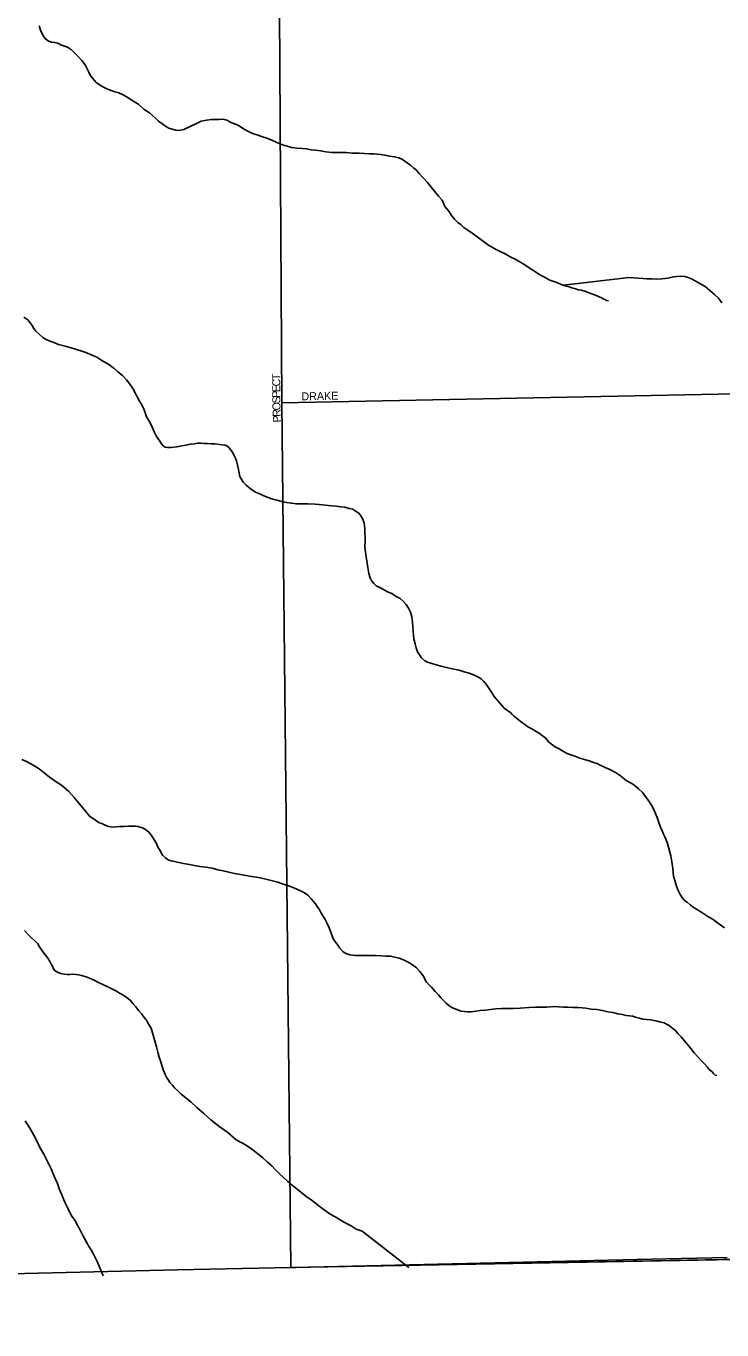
# Model space of a CAD drawing. Extents: x 2010165 to 2382125, y 1060529 to 1407316.
# Drawn here: x 2143376 to 2147720, y 1193411 to 1201555 of the extents above; entities that cross this region are included whole.
import ezdxf

# ---------------------------------------------------------------- set-up
doc = ezdxf.new("R2010")
doc.units = 0
for name, color, linetype in [('GM_X_Adjacent_County', 7, 'Continuous'), ('GM_X_City_Street', 7, 'Continuous'), ('GM_X_City_Street_Text', 7, 'Continuous'), ('GM_X_Corporation', 7, 'Continuous'), ('GM_X_County', 7, 'Continuous'), ('GM_X_Minor_River', 7, 'Continuous')]:
    doc.layers.add(name, color=color, linetype=linetype)

msp = doc.modelspace()

# ---------------------------------------------------------------- linework, layer by layer
at = {"layer": 'GM_X_Adjacent_County'}
msp.add_lwpolyline([(2158006.9, 1194141.9), (2151106.9, 1193912.6), (2145028.4, 1193800.8), (2144321.2, 1193786.8), (2140581.8, 1193696.4), (2139549.1, 1193676.6), (2134076.1, 1193549.4), (2129443.2, 1193492.7), (2126053.1, 1193488.1), (2117908.3, 1193445.4), (2113522.7, 1193410.7)], dxfattribs=at)
at = {"layer": 'GM_X_City_Street'}
for points in [[(2145028.4, 1193800.8), (2144971.9, 1199201.6), (2144945.4, 1203752.3), (2145010.5, 1207323.1)], [(2144971.9, 1199201.6), (2150737.4, 1199316.9)], [(2144321.2, 1193786.9), (2145028.4, 1193800.8), (2145060.2, 1193801.5)], [(2145060.2, 1193801.5), (2147277.4, 1193851.8)], [(2147277.4, 1193851.8), (2147752.4, 1193862.6)], [(2139542.7, 1193667.1), (2140581.8, 1193696.4), (2144321.2, 1193786.9)]]:
    msp.add_lwpolyline(points, dxfattribs=at)
at = {"layer": 'GM_X_Corporation'}
msp.add_lwpolyline([(2154020.1, 1193994.5), (2151351.3, 1193919.5), (2151107.4, 1193912.6), (2150229, 1193893.7), (2145028.4, 1193800.8), (2144321.2, 1193786.8), (2140581.8, 1193696.4), (2139549.1, 1193676.6), (2139563.1, 1207294.1), (2139646.1, 1221239.5)], dxfattribs=at)
at = {"layer": 'GM_X_County'}
msp.add_lwpolyline([(2158006.9, 1194141.9), (2151106.9, 1193912.6), (2145028.4, 1193800.8), (2144321.2, 1193786.8), (2140581.8, 1193696.4), (2139549.1, 1193676.6), (2139521.7, 1198873.5), (2139522.3, 1201475.3), (2139563.1, 1207294.1), (2139553.6, 1210761.2), (2139571.8, 1213893.1), (2139604.7, 1218402.7), (2139646.1, 1221239.5)], dxfattribs=at)
at = {"layer": 'GM_X_Minor_River'}
for points in [[(2143458.3, 1201556.4), (2143466.6, 1201530.4), (2143481.1, 1201498.5), (2143495.4, 1201476.6), (2143507.5, 1201466.7), (2143517.6, 1201460.8), (2143533.7, 1201455), (2143553.8, 1201453.2), (2143573.9, 1201447.5), (2143598.1, 1201435.7), (2143634.3, 1201424.1), (2143658.6, 1201406.4), (2143680.9, 1201386.6), (2143701.2, 1201364.8), (2143723.6, 1201340.9), (2143744, 1201313.1), (2143756.3, 1201287.2), (2143766.5, 1201271.3), (2143774.8, 1201253.3), (2143783, 1201239.4), (2143793.2, 1201227.4), (2143811.5, 1201203.6), (2143833.8, 1201187.8), (2143856, 1201176.1), (2143880.2, 1201162.3), (2143906.3, 1201152.6), (2143930.5, 1201144.9), (2143954.6, 1201137.1), (2143978.8, 1201127.4), (2144007.1, 1201111.7), (2144041.4, 1201088), (2144079.8, 1201064.4), (2144112.2, 1201034.7), (2144146.6, 1201013.1), (2144166.8, 1200995.3), (2144185.1, 1200977.4), (2144203.3, 1200961.6), (2144223.6, 1200945.8), (2144239.8, 1200934), (2144251.9, 1200926.1), (2144268, 1200918.3), (2144288.2, 1200910.5), (2144310.3, 1200904.7), (2144330.3, 1200903), (2144360.3, 1200909.4), (2144440, 1200946.5), (2144469.8, 1200960.9), (2144503.8, 1200967.3), (2144531.8, 1200971.7), (2144555.8, 1200972), (2144579.9, 1200972.3), (2144605.9, 1200972.6), (2144630, 1200966.8), (2144660.3, 1200951.2), (2144700.5, 1200935.6), (2144726.8, 1200917.9), (2144751.1, 1200902.1), (2144773.2, 1200892.4), (2144795.4, 1200882.6), (2144819.6, 1200874.9), (2144845.7, 1200865.2), (2144871.9, 1200857.5), (2144906.1, 1200843.8), (2144942.4, 1200828.2), (2144982.7, 1200810.7), (2145034.9, 1200797.3), (2145069.1, 1200791.7), (2145101.1, 1200790.1), (2145127.2, 1200788.4), (2145155.3, 1200782.7), (2145183.4, 1200779), (2145213.5, 1200775.4), (2145247.7, 1200769.8), (2145287.8, 1200766.3), (2145331.9, 1200764.8), (2145373.9, 1200765.3), (2145412, 1200761.8), (2145456.1, 1200760.3), (2145488.2, 1200758.7), (2145520.3, 1200757.1), (2145546.3, 1200757.4), (2145566.4, 1200755.6), (2145590.5, 1200751.9), (2145616.6, 1200748.2), (2145644.7, 1200742.6), (2145676.8, 1200738.9), (2145703, 1200731.2), (2145725.1, 1200721.5), (2145755.4, 1200701.8), (2145775.7, 1200686), (2145795.9, 1200668.2), (2145812.1, 1200656.3), (2145830.4, 1200634.5)], [(2145830.4, 1200634.5), (2145854.8, 1200606.7), (2145881.3, 1200576.9), (2145950.5, 1200493.5), (2145972.9, 1200467.7), (2145989.4, 1200427.8), (2146015.8, 1200398), (2146032.2, 1200372.1), (2146050.6, 1200348.2), (2146070.8, 1200328.4), (2146091.1, 1200312.6), (2146109.3, 1200296.8), (2146133.6, 1200281.1), (2146159.9, 1200261.3), (2146190.2, 1200239.6), (2146222.6, 1200215.9), (2146257, 1200190.3), (2146301.4, 1200162.7), (2146335.7, 1200147.1), (2146365.9, 1200131.4), (2146398.2, 1200113.8), (2146428.5, 1200098.1), (2146458.7, 1200082.4), (2146489, 1200062.7), (2146517.3, 1200045), (2146549.7, 1200023.3), (2146584, 1200001.7), (2146616.3, 1199984), (2146646.5, 1199968.3), (2146682.8, 1199954.7), (2146709, 1199945), (2146731.1, 1199935.2), (2146749.2, 1199929.4), (2146767.3, 1199925.7), (2146783.4, 1199919.8), (2146799.5, 1199916), (2146811.6, 1199912.2), (2146825.6, 1199908.3), (2146843.7, 1199904.5), (2146863.8, 1199898.8), (2146892, 1199889.1), (2146912.1, 1199881.3), (2146930.3, 1199873.5), (2146944.4, 1199867.6), (2146954.5, 1199863.8), (2146968.5, 1199857.9), (2146978.6, 1199852), (2146988.7, 1199846.1), (2147000.8, 1199840.2), (2147010.9, 1199838.4)], [(2146730.3, 1199935.6), (2147141.2, 1199984.4), (2147169.3, 1199982.8), (2147197.3, 1199981.1), (2147225.4, 1199977.4), (2147251.5, 1199975.7), (2147279.5, 1199976.1), (2147311.6, 1199974.5), (2147345.6, 1199976.9), (2147381.6, 1199981.3), (2147417.6, 1199987.8), (2147459.6, 1199992.3), (2147487.7, 1199990.7), (2147509.8, 1199984.9), (2147530, 1199977.1), (2147552.2, 1199963.4), (2147582.4, 1199947.7), (2147614.7, 1199928), (2147645.1, 1199904.3), (2147673.5, 1199878.6), (2147697.8, 1199854.8), (2147720.2, 1199827)], [(2143361.9, 1199737.4), (2143386.2, 1199719.6), (2143402.5, 1199701.8), (2143414.7, 1199683.9), (2143425, 1199665.9), (2143437.2, 1199650.1), (2143479.8, 1199610.4), (2143498, 1199598.6), (2143520.1, 1199588.9), (2143548.3, 1199579.2), (2143578.5, 1199565.5), (2143620.7, 1199556), (2143657, 1199544.4), (2143691.1, 1199534.8), (2143723.3, 1199525.1), (2143749.5, 1199515.4), (2143773.7, 1199505.7), (2143797.8, 1199496), (2143818, 1199486.2), (2143836.2, 1199474.4), (2143858.4, 1199460.6), (2143886.7, 1199444.9), (2143923, 1199419.2), (2143949.4, 1199395.5), (2143977.8, 1199371.8), (2144002.1, 1199346), (2144024.5, 1199318.2), (2144042.9, 1199290.3), (2144059.4, 1199260.4), (2144071.7, 1199234.5), (2144084, 1199212.6), (2144098.4, 1199188.7), (2144112.8, 1199158.7), (2144127.4, 1199114.8), (2144149.9, 1199076.9), (2144164.4, 1199045), (2144178.7, 1199017.1), (2144189.1, 1198995.1), (2144201.3, 1198977.2), (2144211.5, 1198961.3), (2144221.8, 1198945.4), (2144231.9, 1198933.5), (2144244.1, 1198925.6), (2144260.1, 1198921.8), (2144282.2, 1198922.1), (2144316.2, 1198926.5), (2144346.1, 1198932.9), (2144374.1, 1198937.2), (2144402.1, 1198943.6), (2144428.1, 1198945.9), (2144448.1, 1198950.2), (2144466.1, 1198950.4), (2144486.2, 1198948.6), (2144508.2, 1198946.9), (2144532.3, 1198945.2), (2144554.3, 1198945.4), (2144616.6, 1198936.2), (2144628.6, 1198932.3), (2144644.8, 1198920.5), (2144653, 1198910.6), (2144663.2, 1198896.6)], [(2144663.2, 1198896.6), (2144671.4, 1198880.7), (2144681.7, 1198860.7), (2144690, 1198838.8), (2144696.3, 1198814.8), (2144702.7, 1198784.8), (2144707, 1198764.7), (2144709.2, 1198748.7), (2144715.4, 1198732.7), (2144723.6, 1198720.8), (2144731.7, 1198706.8), (2144739.9, 1198696.9), (2144750, 1198687), (2144762.2, 1198677.1), (2144774.3, 1198667.2), (2144790.5, 1198655.4), (2144808.7, 1198643.6), (2144838.9, 1198631.9), (2144861.1, 1198620.2), (2144887.3, 1198610.4), (2144915.5, 1198600.8), (2144943.6, 1198593.1), (2144971.8, 1198585.4), (2145001.9, 1198579.8), (2145032, 1198574.1), (2145064.1, 1198570.5), (2145098.2, 1198570.9), (2145136.2, 1198571.4), (2145180.3, 1198567.9), (2145206.4, 1198566.2), (2145226.5, 1198564.4), (2145244.5, 1198562.7), (2145264.6, 1198560.9), (2145286.6, 1198559.2), (2145312.7, 1198555.5), (2145340.8, 1198551.8), (2145366.9, 1198550.1), (2145393, 1198542.4), (2145415.2, 1198536.7), (2145433.3, 1198524.8), (2145453.5, 1198513.1), (2145465.8, 1198495.1), (2145478.1, 1198475.2), (2145486.4, 1198449.3), (2145490.8, 1198417.2), (2145491.9, 1198332.9), (2145490.3, 1198306.8), (2145492.6, 1198282.8), (2145497, 1198254.8), (2145503.5, 1198212.7), (2145510.1, 1198172.7), (2145516.6, 1198134.6), (2145524.9, 1198108.6), (2145535.2, 1198086.7), (2145547.4, 1198072.8), (2145561.7, 1198058.9), (2145583.8, 1198047.1), (2145608, 1198035.4), (2145632.3, 1198021.7), (2145658.5, 1198009.9), (2145682.7, 1197994.2), (2145711, 1197978.5), (2145729.2, 1197962.7), (2145749.5, 1197942.8), (2145763.8, 1197918.9), (2145776.2, 1197895), (2145784.6, 1197865), (2145789, 1197831), (2145789.4, 1197800.9), (2145791.8, 1197774.8), (2145794.1, 1197750.8), (2145796.4, 1197726.7), (2145804.8, 1197696.7), (2145811.2, 1197670.7), (2145819.5, 1197646.8), (2145831.8, 1197626.8), (2145844, 1197608.9), (2145862.3, 1197593.1), (2145882.5, 1197581.3), (2145908.6, 1197573.6), (2145936.7, 1197565.9), (2145966.9, 1197556.3), (2146001.1, 1197548.6), (2146035.2, 1197541.1), (2146079.4, 1197531.6), (2146111.6, 1197521.9), (2146141.8, 1197512.2), (2146170, 1197502.6), (2146196.2, 1197490.9), (2146216.4, 1197477.1), (2146234.6, 1197461.2), (2146248.9, 1197443.3), (2146265.2, 1197419.5), (2146281.6, 1197393.6), (2146298, 1197367.7), (2146361, 1197294.2), (2146383.3, 1197278.5), (2146399.4, 1197266.6), (2146409.6, 1197254.7), (2146421.8, 1197244.8), (2146435.9, 1197235)], [(2146435.9, 1197235), (2146450.1, 1197221.1), (2146468.3, 1197207.3), (2146488.5, 1197195.5), (2146508.8, 1197177.7), (2146537, 1197164), (2146557.2, 1197150.2), (2146579.4, 1197138.4), (2146599.7, 1197122.6), (2146619.9, 1197106.8), (2146636.2, 1197086.9), (2146656.5, 1197069.1), (2146678.7, 1197053.3), (2146702.9, 1197039.6), (2146727.2, 1197025.8), (2146757.4, 1197010.2), (2146801.7, 1196994.7), (2146831.9, 1196983), (2146862.1, 1196973.3), (2146892.2, 1196965.7), (2146918.4, 1196956), (2146940.5, 1196948.2), (2146964.7, 1196936.5), (2146990.9, 1196924.7), (2147021.2, 1196911.1), (2147055.5, 1196893.4), (2147087.8, 1196871.8), (2147122.2, 1196842.1), (2147168.6, 1196816.6), (2147199, 1196790.9), (2147223.4, 1196767.1), (2147241.7, 1196745.2), (2147256, 1196725.3), (2147268.3, 1196707.4), (2147280.5, 1196687.5), (2147292.8, 1196665.6), (2147303.2, 1196639.6), (2147315.6, 1196611.7), (2147323.9, 1196585.7), (2147336.4, 1196551.8), (2147346.7, 1196527.8), (2147355, 1196507.8), (2147363.3, 1196489.9), (2147371.5, 1196471.9), (2147379.8, 1196450), (2147400.9, 1196372), (2147407.4, 1196333.9), (2147413.9, 1196291.9), (2147418.5, 1196245.8), (2147429, 1196211.8), (2147437.4, 1196181.8), (2147447.8, 1196155.8), (2147458.1, 1196133.9), (2147470.4, 1196114), (2147484.6, 1196096.1), (2147502.8, 1196082.3), (2147521.1, 1196066.5), (2147541.3, 1196050.6), (2147567.6, 1196034.9), (2147593.8, 1196017.2), (2147632.2, 1195993.6), (2147664.5, 1195973.9), (2147698.9, 1195950.3), (2147735.3, 1195922.6)], [(2143350, 1196974.4), (2143378.3, 1196960.7), (2143406.5, 1196947), (2143430.7, 1196931.2), (2143457, 1196915.5), (2143479.2, 1196899.7), (2143499.5, 1196881.9), (2143521.8, 1196864.1), (2143550.1, 1196844.4), (2143570.3, 1196830.6), (2143590.5, 1196816.8), (2143608.7, 1196803), (2143626.9, 1196789.2), (2143643.2, 1196773.3), (2143659.4, 1196755.4), (2143675.7, 1196735.6), (2143747, 1196650.2), (2143773.4, 1196618.4), (2143801.7, 1196600.7), (2143817.9, 1196588.8), (2143832, 1196579), (2143848.1, 1196573.2), (2143866.3, 1196565.4), (2143884.4, 1196557.6), (2143904.5, 1196553.8), (2143922.5, 1196552), (2143938.6, 1196552.2), (2143958.6, 1196554.5), (2143984.6, 1196554.8), (2144016.6, 1196557.2), (2144036.7, 1196557.4), (2144058.7, 1196557.7), (2144074.7, 1196555.9), (2144086.8, 1196552), (2144102.9, 1196546.2), (2144121.1, 1196536.4), (2144141.3, 1196520.6), (2144159.6, 1196498.7), (2144176, 1196472.9), (2144190.4, 1196448.9), (2144200.7, 1196423), (2144210.9, 1196409.1), (2144217.1, 1196395.1), (2144227.4, 1196377.2), (2144245.6, 1196359.3), (2144259.8, 1196349.5), (2144279.9, 1196341.7), (2144304, 1196336), (2144330.1, 1196330.3), (2144358.3, 1196324.6), (2144396.4, 1196317.1), (2144426.5, 1196311.4), (2144460.7, 1196305.8), (2144498.8, 1196302.2), (2144537, 1196294.7), (2144573.1, 1196285.1), (2144607.3, 1196277.5), (2144641.5, 1196269.9), (2144677.6, 1196262.3), (2144713.8, 1196254.7)], [(2144713.8, 1196254.7), (2144747.9, 1196249.1), (2144784.1, 1196243.6), (2144826.2, 1196236), (2144856.4, 1196230.4), (2144946.8, 1196207.4), (2144981, 1196195.8), (2145017.2, 1196184.2), (2145051.5, 1196170.6), (2145085.7, 1196155), (2145114, 1196141.3), (2145134.2, 1196125.5), (2145156.5, 1196103.7), (2145170.8, 1196087.8), (2145183, 1196071.9), (2145193.2, 1196056), (2145205.5, 1196038), (2145215.7, 1196018.1), (2145228, 1195998.2), (2145240.3, 1195978.3), (2145254.7, 1195950.4), (2145267.1, 1195922.4), (2145281.6, 1195888.5), (2145296.1, 1195848.5), (2145318.5, 1195820.7), (2145334.9, 1195794.8), (2145355.2, 1195773), (2145375.4, 1195759.2), (2145399.5, 1195753.5), (2145427.6, 1195749.8), (2145453.7, 1195750.1), (2145479.7, 1195748.5), (2145505.8, 1195748.8), (2145531.8, 1195749.1), (2145557.8, 1195749.4), (2145593.9, 1195747.9), (2145622, 1195746.2), (2145650.1, 1195744.5), (2145676.2, 1195738.8), (2145704.3, 1195733.2), (2145732.5, 1195721.5), (2145760.7, 1195707.8), (2145789, 1195692.1), (2145813.3, 1195672.3), (2145833.6, 1195650.5), (2145854, 1195622.6), (2145876.6, 1195582.8), (2145907, 1195551.1), (2145929.4, 1195525.2), (2145949.7, 1195503.4), (2145966, 1195485.6), (2145982.3, 1195467.7), (2145998.5, 1195451.9), (2146014.7, 1195438), (2146032.9, 1195424.2), (2146089.3, 1195402.8), (2146113.4, 1195399.1), (2146131.4, 1195397.3), (2146155.5, 1195397.6), (2146183.5, 1195402), (2146211.4, 1195406.3), (2146243.5, 1195408.7), (2146275.5, 1195413.1), (2146309.5, 1195415.5), (2146343.5, 1195418), (2146379.6, 1195418.4), (2146419.6, 1195418.9), (2146459.7, 1195421.4), (2146515.7, 1195424.1), (2146555.8, 1195426.6), (2146591.8, 1195427), (2146623.9, 1195427.4), (2146649.9, 1195429.8), (2146675.9, 1195430.1), (2146702, 1195428.4), (2146730.1, 1195426.7), (2146760.1, 1195427.1), (2146790.2, 1195425.4), (2146824.3, 1195423.9), (2146870.4, 1195420.4), (2146904.5, 1195414.8), (2146938.6, 1195411.2), (2146974.8, 1195405.6), (2147006.9, 1195398), (2147039, 1195392.4), (2147071.2, 1195384.8), (2147097.3, 1195381.1), (2147121.4, 1195375.3), (2147143.5, 1195371.6), (2147163.6, 1195369.8), (2147179.7, 1195364), (2147205.8, 1195358.3), (2147225.9, 1195352.5), (2147250, 1195348.8), (2147274, 1195347.1), (2147296.1, 1195343.4), (2147318.2, 1195339.6), (2147338.3, 1195333.9), (2147358.4, 1195328.1), (2147374.6, 1195320.3), (2147390.7, 1195312.4)], [(2143366, 1195905.1), (2143388.4, 1195881.3), (2143449.3, 1195821.9), (2143459.5, 1195803.9), (2143475.9, 1195778.1), (2143496.3, 1195752.2), (2143512.6, 1195732.3), (2143522.8, 1195716.4), (2143531, 1195700.5), (2143537.1, 1195690.5), (2143543.3, 1195676.6), (2143551.6, 1195658.6), (2143567.8, 1195646.7), (2143579.9, 1195640.9), (2143593.9, 1195637), (2143614, 1195633.3), (2143632.1, 1195631.5), (2143650.1, 1195631.7), (2143668.1, 1195631.9), (2143686.2, 1195630.1), (2143704.2, 1195628.4), (2143722.3, 1195624.6), (2143750.5, 1195616.9), (2143772.6, 1195607.1), (2143800.8, 1195595.4), (2143827.1, 1195581.7), (2143859.3, 1195566.1), (2143889.6, 1195552.4), (2143915.8, 1195538.7), (2143940, 1195526.9), (2143960.2, 1195515.1), (2143980.4, 1195503.3), (2144000.6, 1195489.5), (2144024.9, 1195469.8), (2144043.2, 1195449.9), (2144061.5, 1195428.1), (2144079.8, 1195404.2), (2144098.1, 1195382.4), (2144112.4, 1195362.5), (2144126.7, 1195344.6), (2144136.9, 1195328.7), (2144147.1, 1195312.8), (2144157.4, 1195294.8), (2144182.6, 1195208.9), (2144191, 1195178.8), (2144199.4, 1195144.8), (2144207.8, 1195114.9), (2144216.2, 1195084.9), (2144224.6, 1195056.9), (2144233, 1195030.9), (2144245.3, 1195007), (2144255.6, 1194985), (2144265.8, 1194971.1), (2144274, 1194957.2), (2144290.3, 1194939.3), (2144302.5, 1194923.4)], [(2147390.7, 1195312.4), (2147404.9, 1195300.6), (2147427.1, 1195282.8), (2147445.4, 1195262.9), (2147465.8, 1195241.1), (2147526.8, 1195169.6), (2147547.2, 1195141.8), (2147569.6, 1195116), (2147591.9, 1195092.2), (2147610.2, 1195072.3), (2147628.5, 1195054.5), (2147640.7, 1195036.6), (2147656.9, 1195024.8), (2147667.1, 1195012.8), (2147677.2, 1195002.9), (2147687.3, 1194999)], [(2144302.5, 1194923.4), (2144320.8, 1194905.6), (2144345.1, 1194883.8), (2144373.4, 1194860.1), (2144405.9, 1194832.4), (2144442.3, 1194800.7), (2144484.9, 1194763.1), (2144529.5, 1194723.5), (2144580.1, 1194684), (2144634.7, 1194644.6), (2144687.4, 1194597.1), (2144745.9, 1194567.7), (2144784.3, 1194540.1), (2144820.7, 1194512.4), (2144853.2, 1194484.7), (2144883.6, 1194459), (2144909.9, 1194435.2), (2144932.3, 1194411.4), (2144956.6, 1194387.7), (2144981, 1194363.9), (2145009.4, 1194338.2), (2145039.7, 1194312.4), (2145088.3, 1194272.9), (2145122.7, 1194247.2), (2145155.1, 1194223.6), (2145183.4, 1194201.8), (2145213.8, 1194178.1), (2145244.1, 1194156.4), (2145274.5, 1194134.7), (2145308.8, 1194115.1), (2145343.1, 1194093.4), (2145375.4, 1194075.8), (2145405.7, 1194060.1), (2145436, 1194040.4), (2145474.2, 1194026.8), (2145765.3, 1193799.8)], [(2143369.6, 1194717.3), (2143388, 1194687.4), (2143406.4, 1194659.6), (2143424.9, 1194627.7), (2143443.4, 1194591.8), (2143461.9, 1194549.9), (2143486.5, 1194508.1), (2143503, 1194476.2), (2143517.4, 1194446.2), (2143531.8, 1194416.3), (2143544.2, 1194386.4), (2143556.6, 1194356.4), (2143571.1, 1194324.5), (2143583.5, 1194292.6), (2143600, 1194254.6), (2143616.6, 1194212.7), (2143637.2, 1194170.8), (2143659.9, 1194122.9), (2143682.3, 1194095.1), (2143692.6, 1194071.2), (2143704.9, 1194051.3), (2143715.2, 1194029.3), (2143727.5, 1194005.4), (2143739.8, 1193981.5), (2143756.2, 1193955.6), (2143770.6, 1193929.7), (2143784.9, 1193907.8), (2143793.1, 1193891.8), (2143801.3, 1193875.9), (2143811.6, 1193853.9), (2143817.8, 1193842), (2143822.2, 1193834.9)], [(2143856.2, 1193749.2), (2143822.2, 1193834.9)]]:
    msp.add_lwpolyline(points, dxfattribs=at)

# ---------------------------------------------------------------- texts
at = {"layer": 'GM_X_City_Street_Text'}
for s, rotation, p in [('C', 90, (2144962.9, 1199304)), ('T', 90, (2144962.9, 1199343.5)), ('E', 90, (2144962.9, 1199268.8)), ('P', 90.04099, (2144962.9, 1199233.6)), ('DRAKE', 1.19283, (2145095.3, 1199216.8)), ('S', 90.57377, (2144963.3, 1199198.5)), ('O', 91.82542, (2144964.7, 1199154.8)), ('R', 92.01595, (2144966.1, 1199115.3)), ('P', 92.02202, (2144967.3, 1199080.1))]:
    msp.add_text(s, height=50, rotation=rotation, dxfattribs=at).set_placement(p)

doc.saveas('drawing.dxf')
